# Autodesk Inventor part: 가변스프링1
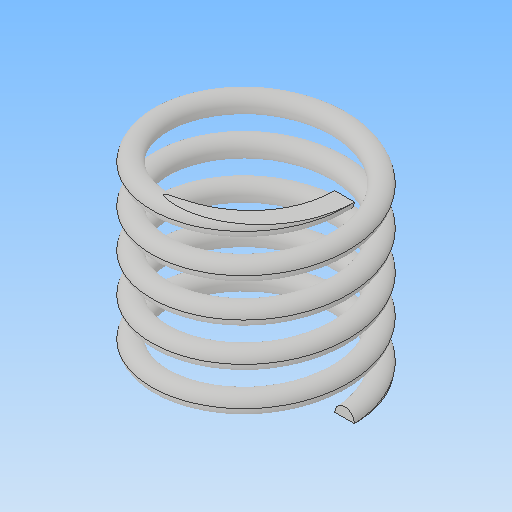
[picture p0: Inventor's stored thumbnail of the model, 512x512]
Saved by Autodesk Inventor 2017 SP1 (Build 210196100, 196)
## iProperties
Part Number: 가변스프링1
Material: 일반
Document SubType Name: Modeling
Designer: MRC
Density: 1 g/cm^3
Appearance: 기본값
Author: MRC
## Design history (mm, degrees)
sketch "스케치1"
  geometry: L1 (0, 0)-(0, 19.5); L2 (0, 0)-(9, 0); L3 (0, 19.5)-(9, 19.5); C1 r 1 at (9, 0)
  constraints: 6 end point, 1 centre point, 1 coincident, 1 parallel, 1 perpendicular, 1 vertical
  dimensions: "d0" = 19.5 distance of L1.start L1.end (derived); "d1" = 9 distance of L1.start L2.end; "d2" = 9 distance of L1.end L3.end; "d3" = 2 diameter of C1
feature "코일1" sketch "스케치1" pitch "d4" = 10; turns "d6" = 5; dims "d5" = 19.5 (= d0), "d7" = 0, angle "d8" = 90 deg, angle "d9" = 90 deg, "d10" = 0, "d11" = 0
sketch "스케치2"
  geometry: L1 (19.5, 20)-(0, 20); L2 (0, 20)-(0, -20); L3 (0, -20)-(19.5, -20); L4 (19.5, -20)-(19.5, 20); 2 further points
  constraints: 8 end point, 2 parallel, 1 coincident, 1 horizontal, 1 midpoint, 1 perpendicular
  dimensions: "d12" = 40 distance of L3.end L1.start; "d13" = 19.5 distance of L2.end L3.end (= d0)
extrude "돌출1" sketch "스케치2" stored distance "d14" = 0; taper "d15" = 0 deg
node "솔리드1"
